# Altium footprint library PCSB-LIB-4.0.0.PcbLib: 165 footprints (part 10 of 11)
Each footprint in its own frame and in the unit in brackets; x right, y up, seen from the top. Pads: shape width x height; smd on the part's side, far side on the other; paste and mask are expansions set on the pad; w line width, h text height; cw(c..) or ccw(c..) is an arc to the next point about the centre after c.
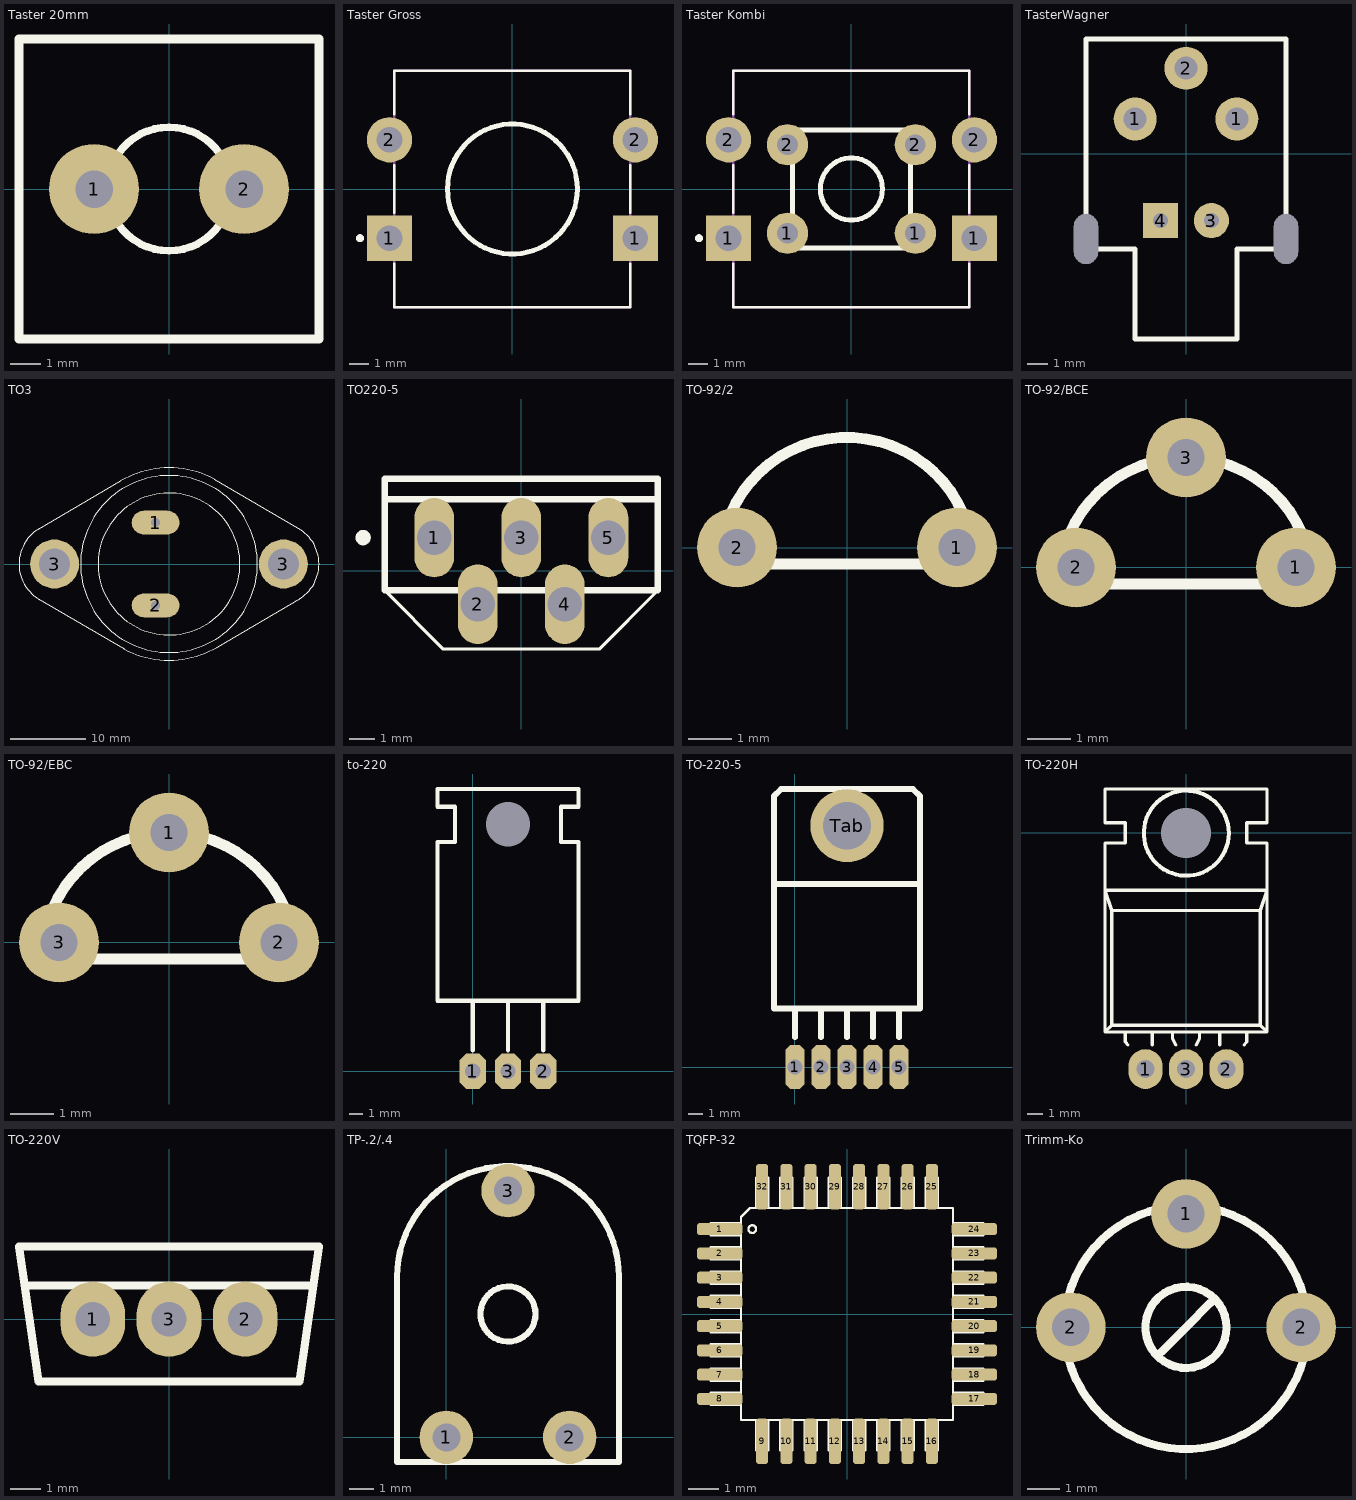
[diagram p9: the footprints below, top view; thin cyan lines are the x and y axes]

## Taster 20mm [mm]
height 20
pads (2):
  round 3 hole 1.25 unplated: 1(-2.5,0) 2(2.5,0)
Top Overlay:
  circle w0.254: c0,0 r2.062
  lines w0.3: -5,-5 5,-5 5,5 -5,5 -5,-5

## Taster Gross [mm]
height 7.8
pads (4):
  rect 2.3x2.3 hole 1.3: 1(-6.25,-2.5) 1(6.25,-2.5)
  round 2.3 hole 1.3: 2(-6.25,2.5) 2(6.25,2.5)
Top Overlay:
  circle w0.2: c-7.75,-2.5 r0.1
  circle w0.254: c0,0 r3.302
  lines w0.127: -6,-3.788 -6,-6 6,-6 6,-3.788 ; -6,-1.212 -6,1.212 ; -6,3.788 -6,6 6,6 6,3.788 ; 6,-1.212 6,1.212
Mechanical 13:
  circle w0.2: c-7.75,-2.5 r0.1
  lines w0.127: -6,-6 -6,6 6,6 6,-6 -6,-6

## Taster Kombi [mm]
height 7.8
pads (8):
  rect 2.3x2.3 hole 1.3: 1(-6.25,-2.5) 1(6.25,-2.5)
  round 2.1 hole 1.05: 1(-3.25,-2.25) 1(3.25,-2.25) 2(-3.25,2.25) 2(3.25,2.25)
  round 2.3 hole 1.3: 2(-6.25,2.5) 2(6.25,2.5)
Top Overlay:
  circle w0.254: c0,0 r1.581
  circle w0.2: c-7.75,-2.5 r0.1
  lines w0.127: -6,-3.788 -6,-6 6,-6 6,-3.788 ; -6,-1.212 -6,1.212 ; -6,3.788 -6,6 6,6 6,3.788 ; 6,-1.212 6,1.212
  lines w0.254: -3,-3 3,-3 3,3 -3,3 -3,-3
Mechanical 13:
  lines w0.127: -6,-6 6,-6 6,6 -6,6 -6,-6

## TasterWagner [mm]
pads (7):
  round 2.15 hole 1.15: 1(-2.54,1.73) 1(2.54,1.73) 2(0,4.27)
  round 1.75 hole 0.75: 3(1.27,-3.35)
  rect 1.75x1.75 hole 0.75: 4(-1.27,-3.35)
  round 0.1 hole 1.2 slot 2.5 at 90 deg: H1(-5,-4.27) H2(5,-4.27)
Top Overlay:
  lines w0.254: -5,-4.77 -5,5.73 5,5.73 5,-4.77 2.54,-4.77 2.54,-9.27 1.065,-9.27 -2.54,-9.27 -2.54,-4.77 -5,-4.77

## TO3 [mil]
pads (4):
  oval 248x124 hole 47.05: 1(-70,215) 2(-70,-215)
  round 255 hole 162: 3(-595,0) 3(595,0)
Top Overlay:
  circle w2: c0,0 r460
  circle w6: c0,0 r369
  lines w6: -680,180 -250,433 cw(c0,0) 0,500 cw(c0,0) 234.74,441.47 ; -679,-181 -234,-442 ; -676.7,-182.58 cw(c-567,0) -780,0 cw(c-567,0) -673.5,184.46 ; -234.74,-441.47 ccw(c0,0) 0,-500 ccw(c0,0) 250,-433.01 ; 235,441 684,178 ; 251,-433 684,-178 ; 683.01,-178.64 ccw(c567,0) 780,0 ccw(c567,0) 683.01,178.64
Mechanical 13:
  circle w6: c-595,0 r85
  circle w6: c595,0 r85

## TO220-5 [mm]
height 16.51
pads (5):
  oval 1.55x3.1 hole 1.35: 1(-3.4,1.3) 2(-1.7,-1.3) 3(0,1.3) 4(1.7,-1.3) 5(3.4,1.3)
Top Overlay:
  circle w0.2: c-6.175,1.3 r0.2
  rectangle: -6.325,1.15 -5.975,1.5
  lines w0.127: -5.335,-0.761 -3.048,-3.048 3.048,-3.048 5.335,-0.761 5.335,3.59 -5.335,3.59 -5.335,-0.761
  lines w0.254: -5.334,2.794 5.334,2.794 ; 5.334,2.794 5.334,-0.762 -5.334,-0.762 -5.334,3.589 -5.335,3.59 5.333,3.59 5.334,3.589 5.334,2.794

## TO-92/2 [mm]
pads (2):
  round 1.85 hole 0.85: 1(2.54,0) 2(-2.54,0)
Top Overlay:
  lines w0.254: -2.927,-0.381 cw(c-0.003,-0.381) 2.921,-0.381 -2.927,-0.381

## TO-92/BCE [mm]
pads (3):
  round 1.85 hole 0.85: 1(2.54,0) 2(-2.54,0) 3(0,2.54)
Top Overlay:
  lines w0.254: -2.927,-0.381 cw(c-0.003,-0.381) 2.921,-0.381 -2.927,-0.381

## TO-92/EBC [mm] "Standard-Transistor wie BC546"
pads (3):
  round 1.85 hole 0.85: 1(0,2.54) 2(2.54,0) 3(-2.54,0)
Top Overlay:
  lines w0.254: -2.927,-0.381 cw(c-0.003,-0.381) 2.921,-0.381 -2.927,-0.381

## to-220 [mm]
pads (4):
  round 0 hole 3.2 unplated: 0(2.537,17.788)
  oct 1.905x2.54 hole 1.1: 1(-0.003,0.008) 2(5.077,0.008) 3(2.537,0.008)
Top Overlay:
  lines w0.305: -0.003,1.532 -0.003,5.088 ; 2.537,1.532 2.537,5.088 ; 5.077,1.532 5.077,5.088 ; -2.543,5.088 -2.543,16.518 -1.273,16.518 -1.273,19.058 -2.543,19.058 -2.543,20.328 7.617,20.328 7.617,19.058 6.347,19.058 6.347,16.518 7.617,16.518 7.617,5.088 -2.543,5.088

## TO-220-5 [mm]
height 5
pads (6):
  oct 1.3x3 hole 1.05: 1(0,0) 2(1.778,0) 3(3.556,0) 4(5.334,0) 5(7.112,0)
  round 5 hole 3.25: Tab(3.556,16.5)
Top Overlay:
  lines w0.4: 0,2.032 0,4 ; 1.778,2.032 1.778,4 ; 3.556,2.032 3.556,4 ; 3.556,16.5 3.556,19 ; 5.334,2.032 5.334,4 ; 7.112,2.032 7.112,4 ; -1.444,12.5 8.556,12.5 ; -1.444,12.5 -1.444,4 8.556,4 8.556,12.5 ; -1.444,12.5 -1.444,18.5 -0.944,19 8.056,19 8.556,18.5 ; 8.556,12.5 8.556,18.5 ; 8.556,18.5 8.556,18.5

## TO-220H [mm]
pads (4):
  round 0 hole 3.15: 0(0,0)
  oval 2.15x2.5 hole 1.15: 1(-2.54,-14.817) 2(2.54,-14.817) 3(0,-14.817)
Top Overlay:
  circle w0.254: c0.017,-0.02 r2.667
  lines w0.2: -3.81,-13.123 -3.81,-12.488 ; -3.762,-13.155 -3.647,-13.317 ; -2.117,-13.317 -2.117,-12.488 ; -0.847,-12.488 -0.847,-12.912 -0.635,-13.317 ; 0.635,-13.317 0.847,-12.912 0.847,-12.488 ; 2.117,-13.317 2.117,-12.488 ; 3.655,-13.317 3.818,-13.099 ; 3.81,-13.123 3.81,-12.488 ; -5.08,-12.488 -5.08,-0.635 -3.81,-0.635 -3.81,0.635 -5.08,0.635 -5.08,2.752 5.08,2.752 5.08,0.635 3.81,0.635 3.81,-0.635 5.08,-0.635 5.08,-12.488 ; -5.08,-12.488 5.08,-12.488 ; -5.08,-12.488 -4.657,-12.065 ; -4.657,-12.065 -4.657,-4.868 ; -4.657,-12.065 4.657,-12.065 ; -4.657,-4.868 -5.08,-3.598 5.08,-3.598 4.657,-4.868 ; -4.657,-4.868 4.657,-4.868 ; 4.657,-12.065 4.657,-4.868 ; 4.657,-12.065 5.08,-12.488

## TO-220V [mm]
pads (3):
  oval 2.15x2.5 hole 1.15: 1(-2.54,0) 2(2.54,0) 3(0,0)
Top Overlay:
  lines w0.254: -4.812,1.125 4.808,1.125 ; -5,2.425 -4.35,-2.075 0,-2.075 4.35,-2.075 5,2.425 0,2.425 -5,2.425

## TP-.2/.4 [mm] "Trimpotentiometer liegend klein"
pads (3):
  round 2.2 hole 1.15: 1(0,0) 2(5.08,0) 3(2.54,10.16)
Top Overlay:
  circle w0.254: c2.54,5.08 r1.136
  lines w0.254: -2.032,-1.016 7.112,-1.016 7.112,6.604 ccw(c2.54,6.604) -2.032,6.604 -2.032,-1.016

## TQFP-32 [mm]
height 1.2
pads (32):
  rrect50% 1.5x0.4 smd: 1(-4.2,2.8) 2(-4.2,2) 3(-4.2,1.2) 4(-4.2,0.4) 5(-4.2,-0.4) 6(-4.2,-1.2) 7(-4.2,-2) 8(-4.2,-2.8) 17(4.2,-2.8) 18(4.2,-2) 19(4.2,-1.2) 20(4.2,-0.4) 21(4.2,0.4) 22(4.2,1.2) 23(4.2,2) 24(4.2,2.8)
  rrect50% 0.4x1.5 smd: 9(-2.8,-4.2) 10(-2,-4.2) 11(-1.2,-4.2) 12(-0.4,-4.2) 13(0.4,-4.2) 14(1.2,-4.2) 15(2,-4.2) 16(2.8,-4.2) 25(2.8,4.2) 26(2,4.2) 27(1.2,4.2) 28(0.4,4.2) 29(-0.4,4.2) 30(-1.2,4.2) 31(-2,4.2) 32(-2.8,4.2)
Top Overlay:
  circle w0.076: c-3.127,2.8 r0.127
  lines w0.076: -3.5,-3 -4.5,-3 -4.5,-2.6 -3.5,-2.6 ; -3.5,-2.2 -4.5,-2.2 ; -3.5,-1.8 -4.5,-1.8 ; -3.5,-1.4 -4.5,-1.4 ; -3.5,-1 -4.5,-1 ; -3.5,-0.6 -4.5,-0.6 ; -3.5,-0.2 -4.5,-0.2 ; -3.5,0.2 -4.5,0.2 ; -3.5,0.6 -4.5,0.6 ; -3.5,1 -4.5,1 ; -3.5,1.4 -4.5,1.4 ; -3.5,1.8 -4.5,1.8 ; -3.5,2.2 -4.5,2.2 ; -3.5,2.6 -4.5,2.6 ; -3.5,3 -4.5,3 ; -3,-3.5 -3,-4.5 -2.6,-4.5 -2.6,-3.5 ; -3,3.5 -3,4.5 -2.6,4.5 -2.6,3.5 ; -2.2,-3.5 -2.2,-4.5 ; -2.2,3.5 -2.2,4.5 ; -1.8,-3.5 -1.8,-4.5 ; -1.8,3.5 -1.8,4.5 ; -1.4,-3.5 -1.4,-4.5 ; -1.4,3.5 -1.4,4.5 ; -1,-3.5 -1,-4.5 ; -1,3.5 -1,4.5 ; -0.6,-3.5 -0.6,-4.5 ; -0.6,3.5 -0.6,4.5 ; 0.2,-3.5 0.2,-4.5 ; 0.2,3.5 0.2,4.5 ; 0.6,-3.5 0.6,-4.5 ; 0.6,3.5 0.6,4.5 ; 1,-3.5 1,-4.5 ; 1,3.5 1,4.5 ; 1.4,-3.5 1.4,-4.5 ; 1.4,3.5 1.4,4.5 ; 1.8,-3.5 1.8,-4.5 2.2,-4.5 2.2,-3.5 ; 1.8,3.5 1.8,4.5 ; 2.2,3.5 2.2,4.5 ; 2.6,-3.5 2.6,-4.5 3,-4.5 3,-3.5 ; 2.6,3.5 2.6,4.5 3,4.5 3,3.5 ; 3.5,-3 4.5,-3 ; 3.5,-2.6 4.5,-2.6 ; 3.5,-2.2 4.5,-2.2 ; 3.5,-1.8 4.5,-1.8 ; 3.5,-1.4 4.5,-1.4 ; 3.5,-1 4.5,-1 ; 3.5,-0.6 4.5,-0.6 ; 3.5,-0.2 4.5,-0.2 ; 3.5,0.2 4.5,0.2 ; 3.5,0.6 4.5,0.6 ; 3.5,1 4.5,1 ; 3.5,1.4 4.5,1.4 ; 3.5,1.8 4.5,1.8 ; 3.5,2.2 4.5,2.2 ; 3.5,2.6 4.5,2.6 4.5,3 3.5,3 ; -4.5,-2.2 -4.5,-1.8 ; -4.5,-2.2 -4.5,-1.8 ; -4.5,-1.4 -4.5,-1 ; -4.5,-1.4 -4.5,-1 ; -4.5,-0.6 -4.5,-0.2 ; -4.5,-0.6 -4.5,-0.2 ; -4.5,0.2 -4.5,0.6 ; -4.5,0.2 -4.5,0.6 ; -4.5,1 -4.5,1.4 ; -4.5,1 -4.5,1.4 ; -4.5,1.8 -4.5,2.2 ; -4.5,1.8 -4.5,2.2 ; -4.5,2.6 -4.5,3 ; -4.5,2.6 -4.5,3 ; -3.5,3.2 -3.5,-3.5 3.5,-3.5 3.5,3.5 -3.2,3.5 ; -3.5,3.2 -3.5,3.2 ; -3.5,3.2 -3.2,3.5 ; -3.5,3.2 -3.2,3.5 ; -2.2,-4.5 -1.8,-4.5 ; -2.2,-4.5 -1.8,-4.5 ; -2.2,4.5 -1.8,4.5 ; -2.2,4.5 -1.8,4.5 ; -1.4,-4.5 -1,-4.5 ; -1.4,-4.5 -1,-4.5 ; -1.4,4.5 -1,4.5 ; -1.4,4.5 -1,4.5 ; -0.6,-4.5 -0.2,-4.5 ; -0.6,-4.5 -0.2,-4.5 ; -0.6,4.5 -0.2,4.5 ; -0.6,4.5 -0.2,4.5 ; -0.2,-4.5 -0.2,-3.5 -0.2,-4.5 ; -0.2,4.5 -0.2,3.5 -0.2,4.5 ; 0.2,-4.5 0.6,-4.5 ; 0.2,-4.5 0.6,-4.5 ; 0.2,4.5 0.6,4.5 ; 0.2,4.5 0.6,4.5 ; 1,-4.5 1.4,-4.5 ; 1,-4.5 1.4,-4.5 ; 1,4.5 1.4,4.5 ; 1,4.5 1.4,4.5 ; 1.8,4.5 2.2,4.5 ; 1.8,4.5 2.2,4.5 ; 4.5,-3 4.5,-2.6 ; 4.5,-3 4.5,-2.6 ; 4.5,-2.2 4.5,-1.8 ; 4.5,-2.2 4.5,-1.8 ; 4.5,-1.4 4.5,-1 ; 4.5,-1.4 4.5,-1 ; 4.5,-0.6 4.5,-0.2 ; 4.5,-0.6 4.5,-0.2 ; 4.5,0.2 4.5,0.6 ; 4.5,0.2 4.5,0.6 ; 4.5,1 4.5,1.4 ; 4.5,1 4.5,1.4 ; 4.5,1.8 4.5,2.2 ; 4.5,1.8 4.5,2.2

## Trimm-Ko [mm]
pads (3):
  round 2.15 hole 1.15: 1(0,3.5) 2(-3.55,0) 2(3.55,0)
Top Overlay:
  circle w0.254: c0,0 r1.25
  circle w0.254: c0,0 r3.75
  lines w0.254: -0.762,-0.762 0,0 0.762,0.762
